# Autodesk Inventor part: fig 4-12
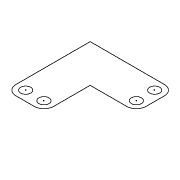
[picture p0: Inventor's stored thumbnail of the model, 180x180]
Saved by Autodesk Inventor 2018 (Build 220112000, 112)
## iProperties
Created: 2005-02
Part Number: fig 4-12
Document SubType Name: Modeling
Designer: CADCIM
Manufacturer: Standard
Standards Organization: Custom
Density: 1 g/cm^3
Material: Generic
Appearance: Default
Author: CADCIM
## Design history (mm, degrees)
sketch "Sketch1"
  geometry: L1 (5.141, 24.979)-(-32.827, 24.979); L2 (-32.827, 24.979)-(-32.827, -12.989); L3 (-27.827, -17.989)-(-18.492, -17.989); L4 (-13.492, -12.989)-(-13.492, 5.644); L5 (-13.492, 5.644)-(5.141, 5.644); L6 (10.141, 10.644)-(10.141, 19.979); C1 r 2.58 at (-27.827, -12.989); C2 r 2.58 at (-18.492, -12.989); C3 r 2.58 at (5.141, 10.644); C4 r 2.58 at (5.141, 19.979); A1 r 5 centre (-27.827, -12.989) between (-32.827, -12.989) and (-27.827, -17.989); A2 r 5 centre (-18.492, -12.989) between (-18.492, -17.989) and (-13.492, -12.989); A3 r 5 centre (5.141, 10.644) between (5.141, 5.644) and (10.141, 10.644); A4 r 5 centre (5.141, 19.979) between (10.141, 19.979) and (5.141, 24.979)
  constraints: 12 end point, 8 centre point, 8 point on circle, 8 tangent, 4 equal radius, 4 parallel, 3 perpendicular, 2 coincident, 1 horizontal
